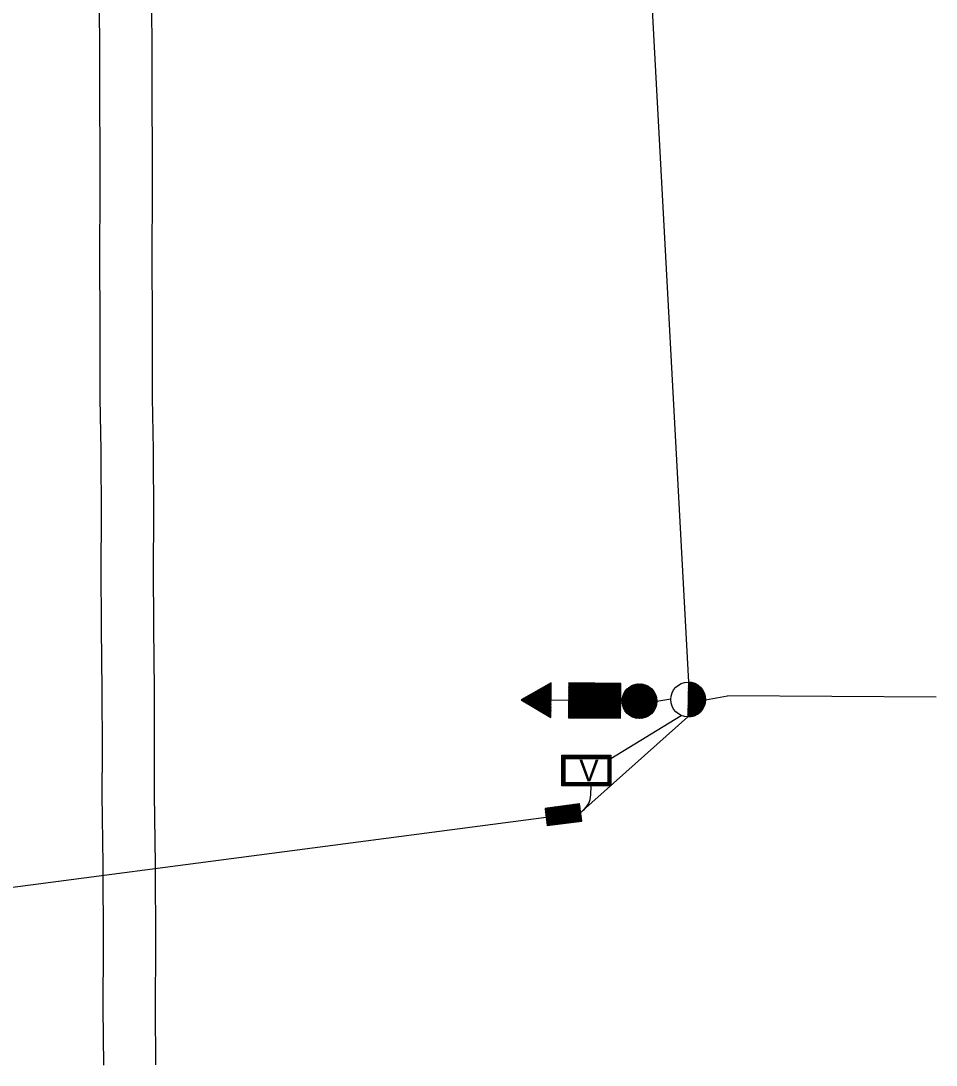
# Model space of a CAD drawing. Extents: x 584850 to 602551, y 145475 to 158627.
# Drawn here: x 585761.3 to 585971.5, y 156212.3 to 156452.1 of the extents above; entities that cross this region are included whole.
import ezdxf

# ---------------------------------------------------------------- set-up
doc = ezdxf.new("R2010")
doc.units = 0
doc.layers.add('Default', color=7, linetype='Continuous')
doc.layers.add('P_ML_LANE_LINE_50', color=7, linetype='Continuous')

msp = doc.modelspace()

# ---------------------------------------------------------------- linework, layer by layer
at = {"layer": 'Default'}
for p, q in [((585893.9, 156683.83), (585914.58, 156300.29)), ((585877.66, 156295.3), (585881.81, 156299.38)), ((585877.87, 156295.18), (585882.62, 156299.84)), ((585878.08, 156295.05), (585883.09, 156299.96)), ((585878.3, 156294.92), (585883.09, 156299.62)), ((585878.51, 156294.8), (585883.08, 156299.28)), ((585883.06, 156297.37), (585881.35, 156299.12)), ((585883.07, 156297.71), (585881.57, 156299.24)), ((585883.07, 156298.05), (585881.79, 156299.36)), ((585883.07, 156298.39), (585882, 156299.48)), ((585883.08, 156298.73), (585882.22, 156299.61)), ((585883.08, 156299.07), (585882.43, 156299.73)), ((585883.09, 156299.41), (585882.65, 156299.85)), ((585883.09, 156299.75), (585882.87, 156299.97)), ((585883.09, 156300.09), (585883.08, 156300.1)), ((585887.01, 156292.1), (585895.09, 156300.02)), ((585887.01, 156292.44), (585894.75, 156300.02)), ((585887.02, 156293.12), (585894.07, 156300.03)), ((585887.02, 156293.45), (585893.73, 156300.03)), ((585887.02, 156292.78), (585894.41, 156300.02)), ((585887.03, 156294.13), (585893.05, 156300.04)), ((585887.03, 156294.47), (585892.72, 156300.04)), ((585887.03, 156293.79), (585893.39, 156300.03)), ((585887.04, 156295.15), (585892.04, 156300.05)), ((585887.04, 156294.81), (585892.38, 156300.04)), ((585887.05, 156296.17), (585891.02, 156300.06)), ((585887.05, 156295.49), (585891.7, 156300.05)), ((585887.05, 156295.83), (585891.36, 156300.05)), ((585887.06, 156297.19), (585890, 156300.07)), ((585887.06, 156296.51), (585890.68, 156300.06)), ((585887.06, 156296.85), (585890.34, 156300.06)), ((585887.07, 156298.21), (585888.98, 156300.08)), ((585887.07, 156297.53), (585889.66, 156300.07)), ((585887.07, 156297.87), (585889.32, 156300.07)), ((585887.08, 156299.22), (585887.96, 156300.09)), ((585887.08, 156298.88), (585888.3, 156300.08)), ((585887.08, 156298.55), (585888.64, 156300.08)), ((585894.14, 156292.03), (585887.08, 156299.22)), ((585887.09, 156299.56), (585887.62, 156300.09)), ((585887.09, 156299.9), (585887.29, 156300.09)), ((585894.82, 156292.02), (585887.09, 156299.9)), ((585894.48, 156292.02), (585887.09, 156299.56)), ((585895.16, 156292.01), (585887.24, 156300.1)), ((585887.35, 156292.09), (585895.43, 156300.01)), ((585895.5, 156292.01), (585887.58, 156300.09)), ((585887.69, 156292.09), (585895.77, 156300.01)), ((585895.84, 156292.01), (585887.92, 156300.09)), ((585888.03, 156292.09), (585896.11, 156300.01)), ((585896.17, 156292), (585888.26, 156300.09)), ((585888.37, 156292.08), (585896.45, 156300)), ((585896.51, 156292), (585888.6, 156300.08)), ((585888.71, 156292.08), (585896.79, 156300)), ((585896.85, 156292), (585888.93, 156300.08)), ((585889.05, 156292.08), (585897.13, 156300)), ((585897.19, 156291.99), (585889.27, 156300.07)), ((585889.39, 156292.07), (585897.47, 156299.99)), ((585897.53, 156291.99), (585889.61, 156300.07)), ((585889.73, 156292.07), (585897.81, 156299.99)), ((585897.87, 156291.99), (585889.95, 156300.07)), ((585890.07, 156292.07), (585898.15, 156299.99)), ((585898.21, 156291.98), (585890.29, 156300.06)), ((585890.4, 156292.06), (585898.49, 156299.98)), ((585898.55, 156291.98), (585890.63, 156300.06)), ((585890.74, 156292.06), (585898.82, 156299.98)), ((585898.89, 156291.98), (585890.97, 156300.06)), ((585891.08, 156292.06), (585899.09, 156299.9)), ((585899.01, 156292.19), (585891.31, 156300.05)), ((585891.42, 156292.05), (585899.09, 156299.56)), ((585899.02, 156292.53), (585891.65, 156300.05)), ((585891.76, 156292.05), (585899.08, 156299.22)), ((585899.02, 156292.87), (585891.99, 156300.05)), ((585899.02, 156293.21), (585892.33, 156300.04)), ((585899.03, 156293.55), (585892.67, 156300.04)), ((585899.03, 156293.89), (585893.01, 156300.04)), ((585899.03, 156294.23), (585893.35, 156300.03)), ((585899.04, 156294.57), (585893.69, 156300.03)), ((585899.04, 156294.91), (585894.03, 156300.03)), ((585899.04, 156295.25), (585894.36, 156300.02)), ((585899.05, 156295.59), (585894.7, 156300.02)), ((585899.05, 156295.93), (585895.04, 156300.02)), ((585899.05, 156296.27), (585895.38, 156300.01)), ((585899.06, 156296.61), (585895.72, 156300.01)), ((585899.06, 156296.95), (585896.06, 156300.01)), ((585899.06, 156297.29), (585896.4, 156300)), ((585899.07, 156297.62), (585896.74, 156300)), ((585899.07, 156297.96), (585897.08, 156300)), ((585899.07, 156298.3), (585897.42, 156299.99)), ((585899.08, 156298.64), (585897.76, 156299.99)), ((585899.08, 156298.98), (585898.1, 156299.99)), ((585899.09, 156299.32), (585898.44, 156299.98)), ((585899.09, 156299.66), (585898.78, 156299.98)), ((585899.34, 156296.03), (585903.29, 156299.91)), ((585899.35, 156295.71), (585903.61, 156299.89)), ((585899.37, 156296.41), (585902.92, 156299.88)), ((585899.37, 156295.39), (585903.92, 156299.86)), ((585899.42, 156295.11), (585904.21, 156299.8)), ((585899.43, 156296.8), (585902.51, 156299.82)), ((585899.48, 156294.83), (585904.48, 156299.73)), ((585899.57, 156294.58), (585904.74, 156299.65)), ((585899.58, 156297.28), (585902.05, 156299.7)), ((585899.66, 156294.34), (585904.97, 156299.54)), ((585899.76, 156294.1), (585905.21, 156299.44)), ((585899.87, 156297.9), (585901.43, 156299.44)), ((585899.89, 156293.89), (585905.42, 156299.31)), ((585900.02, 156293.68), (585905.62, 156299.17)), ((585906.44, 156293.42), (585900.89, 156299.08)), ((585906.59, 156293.61), (585901.1, 156299.22)), ((585906.72, 156293.82), (585901.3, 156299.35)), ((585906.85, 156294.03), (585901.52, 156299.47)), ((585906.96, 156294.27), (585901.75, 156299.58)), ((585907.06, 156294.51), (585901.99, 156299.68)), ((585907.15, 156294.76), (585902.25, 156299.75)), ((585907.21, 156295.03), (585902.52, 156299.82)), ((585907.28, 156295.31), (585902.81, 156299.87)), ((585907.3, 156295.63), (585903.12, 156299.9)), ((585907.32, 156295.95), (585903.45, 156299.91)), ((585907.29, 156296.33), (585903.82, 156299.87)), ((585907.24, 156296.72), (585904.22, 156299.8)), ((585907.1, 156297.21), (585904.68, 156299.68)), ((585906.83, 156297.83), (585905.29, 156299.4)), ((585914.58, 156300.29), (585914.43, 156292.29)), ((585914.51, 156296.63), (585917.21, 156299.22)), ((585914.51, 156296.29), (585917.38, 156299.06)), ((585914.52, 156297.31), (585916.84, 156299.53)), ((585914.52, 156296.97), (585917.02, 156299.38)), ((585914.53, 156297.65), (585916.63, 156299.66)), ((585914.54, 156298.32), (585916.19, 156299.91)), ((585914.54, 156297.99), (585916.41, 156299.79)), ((585914.55, 156298.66), (585915.94, 156300.01)), ((585914.56, 156299.34), (585915.42, 156300.17)), ((585914.56, 156299), (585915.69, 156300.1)), ((585918.4, 156295.36), (585914.56, 156299.34)), ((585914.57, 156299.68), (585915.13, 156300.23)), ((585918.44, 156295.66), (585914.57, 156299.68)), ((585914.58, 156300.29), (585914.58, 156300.29)), ((585914.58, 156300.29), (585914.58, 156300.29)), ((585914.58, 156300.02), (585914.84, 156300.27)), ((585918.49, 156295.96), (585914.58, 156300.02)), ((585918.49, 156296.3), (585914.66, 156300.28)), ((585918.48, 156296.66), (585915.02, 156300.25)), ((585918.41, 156297.08), (585915.43, 156300.17)), ((585918.29, 156297.55), (585915.91, 156300.02)), ((585918.02, 156298.17), (585916.53, 156299.72)), ((585876.37, 156296.06), (585876.97, 156296.65)), ((585876.59, 156295.94), (585877.78, 156297.1)), ((585876.8, 156295.81), (585878.58, 156297.56)), ((585877.01, 156295.68), (585879.39, 156298.01)), ((585879.36, 156294.3), (585877.02, 156296.68)), ((585877.23, 156295.56), (585880.2, 156298.47)), ((585880.15, 156293.83), (585877.24, 156296.8)), ((585877.44, 156295.43), (585881.01, 156298.92)), ((585880.95, 156293.36), (585877.46, 156296.92)), ((585881.75, 156292.88), (585877.67, 156297.04)), ((585882.55, 156292.41), (585877.89, 156297.17)), ((585883.01, 156292.28), (585878.11, 156297.29)), ((585883.02, 156292.62), (585878.32, 156297.41)), ((585883.02, 156292.96), (585878.54, 156297.53)), ((585878.73, 156294.67), (585883.08, 156298.94)), ((585883.02, 156293.3), (585878.76, 156297.65)), ((585878.94, 156294.55), (585883.08, 156298.6)), ((585883.03, 156293.64), (585878.97, 156297.78)), ((585879.15, 156294.42), (585883.07, 156298.26)), ((585883.03, 156293.98), (585879.19, 156297.9)), ((585879.37, 156294.29), (585883.07, 156297.92)), ((585883.03, 156294.32), (585879.41, 156298.02)), ((585879.58, 156294.17), (585883.07, 156297.58)), ((585883.04, 156294.66), (585879.62, 156298.14)), ((585879.79, 156294.04), (585883.06, 156297.24)), ((585883.04, 156295), (585879.84, 156298.26)), ((585880.01, 156293.91), (585883.06, 156296.9)), ((585883.04, 156295.34), (585880.05, 156298.39)), ((585883.05, 156295.68), (585880.27, 156298.51)), ((585883.05, 156296.01), (585880.49, 156298.63)), ((585883.05, 156296.35), (585880.7, 156298.75)), ((585883.06, 156296.69), (585880.92, 156298.87)), ((585883.06, 156297.03), (585881.14, 156299)), ((585892.1, 156292.05), (585887.06, 156297.19)), ((585891.76, 156292.05), (585887.06, 156296.85)), ((585893.12, 156292.04), (585887.07, 156298.21)), ((585892.78, 156292.04), (585887.07, 156297.87)), ((585892.44, 156292.04), (585887.07, 156297.53)), ((585893.8, 156292.03), (585887.08, 156298.88)), ((585893.46, 156292.03), (585887.08, 156298.55)), ((585892.1, 156292.05), (585899.08, 156298.89)), ((585892.44, 156292.04), (585899.08, 156298.55)), ((585892.78, 156292.04), (585899.07, 156298.21)), ((585893.12, 156292.04), (585899.07, 156297.87)), ((585893.46, 156292.03), (585899.07, 156297.53)), ((585893.8, 156292.03), (585899.06, 156297.19)), ((585894.14, 156292.03), (585899.06, 156296.85)), ((585904.13, 156292.01), (585899.43, 156296.81)), ((585904.4, 156292.07), (585899.51, 156297.07)), ((585904.66, 156292.16), (585899.59, 156297.32)), ((585904.91, 156292.24), (585899.69, 156297.56)), ((585905.13, 156292.36), (585899.81, 156297.79)), ((585905.35, 156292.48), (585899.93, 156298.01)), ((585905.56, 156292.6), (585900.07, 156298.21)), ((585900.16, 156293.48), (585905.82, 156299.03)), ((585905.75, 156292.75), (585900.21, 156298.41)), ((585900.32, 156293.3), (585906, 156298.87)), ((585905.94, 156292.9), (585900.36, 156298.6)), ((585900.47, 156293.12), (585906.17, 156298.7)), ((585906.12, 156293.06), (585900.54, 156298.76)), ((585900.65, 156292.96), (585906.35, 156298.54)), ((585906.28, 156293.24), (585900.71, 156298.93)), ((585900.84, 156292.8), (585906.49, 156298.34)), ((585901.02, 156292.65), (585906.63, 156298.14)), ((585901.23, 156292.52), (585906.77, 156297.94)), ((585901.45, 156292.4), (585906.88, 156297.72)), ((585901.67, 156292.28), (585906.99, 156297.49)), ((585901.92, 156292.18), (585907.09, 156297.25)), ((585902.17, 156292.09), (585907.17, 156296.99)), ((585902.44, 156292.02), (585907.24, 156296.73)), ((585914.44, 156292.9), (585918.47, 156296.78)), ((585914.45, 156293.57), (585918.36, 156297.34)), ((585914.45, 156293.23), (585918.42, 156297.06)), ((585914.46, 156293.91), (585918.28, 156297.59)), ((585914.47, 156294.59), (585918.08, 156298.07)), ((585914.47, 156294.25), (585918.18, 156297.83)), ((585914.48, 156294.93), (585917.96, 156298.28)), ((585914.49, 156295.61), (585917.69, 156298.69)), ((585914.49, 156295.27), (585917.83, 156298.49)), ((585914.5, 156295.95), (585917.54, 156298.88)), ((585917.74, 156293.96), (585914.52, 156297.31)), ((585917.6, 156293.77), (585914.52, 156296.97)), ((585917.89, 156294.16), (585914.53, 156297.65)), ((585918.12, 156294.61), (585914.54, 156298.32)), ((585918.01, 156294.38), (585914.54, 156297.99)), ((585918.23, 156294.85), (585914.55, 156298.66)), ((585918.31, 156295.1), (585914.56, 156299)), ((585918.5, 156296.21), (585923.55, 156297.1)), ((585876.16, 156296.19), (585876.16, 156296.19)), ((585876.96, 156295.72), (585876.38, 156296.31)), ((585877.76, 156295.24), (585876.59, 156296.43)), ((585878.56, 156294.77), (585876.81, 156296.56)), ((585880.22, 156293.79), (585883.06, 156296.56)), ((585880.44, 156293.66), (585883.05, 156296.22)), ((585880.65, 156293.53), (585883.05, 156295.89)), ((585880.86, 156293.41), (585883.05, 156295.55)), ((585881.08, 156293.28), (585883.04, 156295.21)), ((585881.29, 156293.15), (585883.04, 156294.87)), ((585881.51, 156293.03), (585883.04, 156294.53)), ((585887.05, 156296.1), (585883.05, 156296.14)), ((585889.39, 156292.07), (585887.03, 156294.47)), ((585890.07, 156292.07), (585887.04, 156295.15)), ((585889.73, 156292.07), (585887.04, 156294.81)), ((585891.08, 156292.06), (585887.05, 156296.17)), ((585890.74, 156292.06), (585887.05, 156295.83)), ((585890.4, 156292.06), (585887.05, 156295.49)), ((585891.42, 156292.05), (585887.06, 156296.51)), ((585894.48, 156292.02), (585899.06, 156296.51)), ((585894.82, 156292.02), (585899.05, 156296.17)), ((585895.16, 156292.01), (585899.05, 156295.83)), ((585895.5, 156292.01), (585899.05, 156295.49)), ((585895.84, 156292.01), (585899.04, 156295.15)), ((585896.17, 156292), (585899.04, 156294.81)), ((585896.51, 156292), (585899.04, 156294.47)), ((585903.54, 156291.93), (585899.34, 156296.21)), ((585903.2, 156291.93), (585899.34, 156295.87)), ((585902.84, 156291.95), (585899.35, 156295.51)), ((585903.84, 156291.96), (585899.38, 156296.51)), ((585902.43, 156292.03), (585899.43, 156295.09)), ((585901.95, 156292.17), (585899.55, 156294.62)), ((585902.73, 156291.97), (585907.28, 156296.43)), ((585903.03, 156291.93), (585907.31, 156296.13)), ((585903.37, 156291.93), (585907.31, 156295.79)), ((585903.73, 156291.94), (585907.29, 156295.43)), ((585904.14, 156292.01), (585907.21, 156295.01)), ((585904.62, 156292.15), (585907.07, 156294.55)), ((585910.51, 156296.36), (585907.33, 156295.87)), ((585914.44, 156292.56), (585918.49, 156296.46)), ((585916.28, 156292.71), (585914.47, 156294.59)), ((585916.05, 156292.61), (585914.47, 156294.25)), ((585916.5, 156292.83), (585914.48, 156294.93)), ((585916.91, 156293.1), (585914.49, 156295.61)), ((585916.71, 156292.97), (585914.49, 156295.27)), ((585917.09, 156293.25), (585914.5, 156295.95)), ((585917.45, 156293.58), (585914.51, 156296.63)), ((585917.27, 156293.42), (585914.51, 156296.29)), ((585914.51, 156292.29), (585918.5, 156296.13)), ((585914.88, 156292.32), (585918.46, 156295.76)), ((585915.29, 156292.38), (585918.4, 156295.37)), ((585915.75, 156292.49), (585918.24, 156294.89)), ((585916.37, 156292.75), (585917.95, 156294.27)), ((585881.72, 156292.9), (585883.03, 156294.19)), ((585881.93, 156292.78), (585883.03, 156293.85)), ((585882.15, 156292.65), (585883.03, 156293.51)), ((585882.36, 156292.52), (585883.02, 156293.17)), ((585882.58, 156292.4), (585883.02, 156292.83)), ((585882.79, 156292.27), (585883.02, 156292.49)), ((585883, 156292.14), (585883.01, 156292.15)), ((585887.35, 156292.09), (585887.01, 156292.44)), ((585888.37, 156292.08), (585887.02, 156293.45)), ((585888.03, 156292.09), (585887.02, 156293.12)), ((585887.69, 156292.09), (585887.02, 156292.78)), ((585889.05, 156292.08), (585887.03, 156294.13)), ((585888.71, 156292.08), (585887.03, 156293.79)), ((585890.29, 156270.71), (585914.43, 156292.29)), ((585896.8, 156282.71), (585912.91, 156292.62)), ((585896.85, 156292), (585899.03, 156294.13)), ((585897.19, 156291.99), (585899.03, 156293.79)), ((585897.53, 156291.99), (585899.03, 156293.45)), ((585897.87, 156291.99), (585899.02, 156293.12)), ((585898.21, 156291.98), (585899.02, 156292.78)), ((585898.55, 156291.98), (585899.02, 156292.44)), ((585898.89, 156291.98), (585899.01, 156292.1)), ((585901.33, 156292.46), (585899.83, 156294)), ((585905.25, 156292.42), (585906.79, 156293.93)), ((585914.47, 156292.29), (585914.43, 156292.33)), ((585914.99, 156292.33), (585914.44, 156292.9)), ((585914.68, 156292.31), (585914.44, 156292.56)), ((585915.55, 156292.44), (585914.45, 156293.57)), ((585915.28, 156292.37), (585914.45, 156293.23)), ((585915.81, 156292.51), (585914.46, 156293.91)), ((585892.17, 156274.41), (585892.25, 156276.44)), ((585881.7, 156271.03), (585881.92, 156271.33)), ((585885.88, 156267.82), (585881.7, 156271.03)), ((585886.22, 156267.86), (585881.73, 156271.3)), ((585881.74, 156270.69), (585882.26, 156271.37)), ((585885.55, 156267.77), (585881.74, 156270.69)), ((585881.78, 156270.36), (585882.6, 156271.42)), ((585885.21, 156267.73), (585881.78, 156270.36)), ((585881.83, 156270.02), (585882.93, 156271.46)), ((585881.87, 156269.69), (585883.27, 156271.51)), ((585881.92, 156269.35), (585883.61, 156271.55)), ((585881.96, 156269.01), (585883.94, 156271.6)), ((585882.01, 156268.68), (585884.28, 156271.64)), ((585882.05, 156268.34), (585884.62, 156271.68)), ((585886.56, 156267.9), (585882.07, 156271.35)), ((585882.09, 156268), (585884.95, 156271.73)), ((585882.14, 156267.67), (585885.29, 156271.77)), ((585882.18, 156267.33), (585885.63, 156271.82)), ((585886.89, 156267.95), (585882.41, 156271.39)), ((585882.52, 156267.37), (585885.96, 156271.86)), ((585887.23, 156267.99), (585882.74, 156271.44)), ((585882.86, 156267.42), (585886.3, 156271.91)), ((585887.57, 156268.04), (585883.08, 156271.48)), ((585883.19, 156267.46), (585886.64, 156271.95)), ((585887.9, 156268.08), (585883.42, 156271.53)), ((585883.53, 156267.51), (585886.97, 156271.99)), ((585888.24, 156268.13), (585883.75, 156271.57)), ((585883.86, 156267.55), (585887.31, 156272.04)), ((585888.58, 156268.17), (585884.09, 156271.61)), ((585884.2, 156267.6), (585887.65, 156272.08)), ((585888.91, 156268.21), (585884.42, 156271.66)), ((585884.54, 156267.64), (585887.98, 156272.13)), ((585889.25, 156268.26), (585884.76, 156271.7)), ((585884.87, 156267.68), (585888.32, 156272.17)), ((585889.59, 156268.3), (585885.1, 156271.75)), ((585885.21, 156267.73), (585888.65, 156272.22)), ((585889.92, 156268.35), (585885.43, 156271.79)), ((585885.55, 156267.77), (585888.99, 156272.26)), ((585890.09, 156268.52), (585885.77, 156271.84)), ((585885.88, 156267.82), (585889.33, 156272.3)), ((585890.05, 156268.85), (585886.11, 156271.88)), ((585886.22, 156267.86), (585889.6, 156272.27)), ((585890.01, 156269.19), (585886.44, 156271.92)), ((585886.56, 156267.9), (585889.65, 156271.93)), ((585889.96, 156269.53), (585886.78, 156271.97)), ((585886.89, 156267.95), (585889.69, 156271.59)), ((585889.92, 156269.86), (585887.12, 156272.01)), ((585887.23, 156267.99), (585889.73, 156271.26)), ((585889.87, 156270.2), (585887.45, 156272.06)), ((585887.57, 156268.04), (585889.78, 156270.92)), ((585889.83, 156270.54), (585887.79, 156272.1)), ((585887.9, 156268.08), (585889.82, 156270.58)), ((585889.78, 156270.87), (585888.13, 156272.15)), ((585889.74, 156271.21), (585888.46, 156272.19)), ((585889.7, 156271.55), (585888.8, 156272.23)), ((585889.65, 156271.88), (585889.14, 156272.28)), ((585889.61, 156272.22), (585889.47, 156272.32)), ((585889.85, 156270.36), (585890.29, 156270.71)), ((585616.41, 156234.38), (585881.92, 156269.31)), ((585884.87, 156267.68), (585881.83, 156270.02)), ((585884.54, 156267.64), (585881.87, 156269.69)), ((585884.2, 156267.6), (585881.92, 156269.35)), ((585883.86, 156267.55), (585881.96, 156269.01)), ((585883.53, 156267.51), (585882.01, 156268.68)), ((585883.19, 156267.46), (585882.05, 156268.34)), ((585882.86, 156267.42), (585882.09, 156268)), ((585888.24, 156268.13), (585889.87, 156270.25)), ((585888.58, 156268.17), (585889.91, 156269.91)), ((585888.91, 156268.21), (585889.96, 156269.57)), ((585889.25, 156268.26), (585890, 156269.24)), ((585889.59, 156268.3), (585890.04, 156268.9)), ((585889.92, 156268.35), (585890.09, 156268.56)), ((585882.52, 156267.37), (585882.14, 156267.67))]:
    msp.add_line(p, q, dxfattribs=at)
for points in [[(585883.01, 156292.14), (585883.09, 156300.1), (585876.16, 156296.19)], [(585899.09, 156299.98), (585887.09, 156300.1), (585887.01, 156292.1), (585899.01, 156291.98)], [(585885.5, 156283.49), (585896.8, 156283.49), (585896.8, 156276.44), (585885.5, 156276.44)], [(585885.75, 156283.24), (585896.55, 156283.24), (585896.55, 156276.69), (585885.75, 156276.69)], [(585886, 156282.99), (585896.3, 156282.99), (585896.3, 156276.94), (585886, 156276.94)], [(585886.25, 156282.74), (585896.05, 156282.74), (585896.05, 156277.19), (585886.25, 156277.19)], [(585889.59, 156272.34), (585881.66, 156271.3), (585882.18, 156267.33), (585890.11, 156268.37)]]:
    msp.add_lwpolyline(points, close=True, dxfattribs=at)
msp.add_lwpolyline([(585971.47, 156296.84), (585923.55, 156297.1)], dxfattribs=at)
for centre in [(585903.33, 156295.91), (585914.51, 156296.29)]:
    msp.add_circle(centre, 4, dxfattribs=at)
for centre, radius, start, end in [((585914.51, 156296.29), 4, 268.9257, 88.9257), ((585887.17, 156274.62), 5, 308.5959, 357.6663)]:
    msp.add_arc(centre, radius, start, end, dxfattribs=at)
at = {"layer": 'P_ML_LANE_LINE_50'}
for points in [[(585780.31, 156212.33), (585780.21, 156225.36), (585780.29, 156239.83), (585780.19, 156258.39), (585779.95, 156274.44), (585779.99, 156284.52), (585779.94, 156298.41), (585779.78, 156312.7), (585779.74, 156326.93), (585779.78, 156337.72), (585779.7, 156353.5), (585779.49, 156365.49), (585779.47, 156382.8), (585779.4, 156397.71), (585779.48, 156413.36), (585779.41, 156442.31), (585779.36, 156458.78)], [(585792.31, 156212.43), (585792.21, 156225.37), (585792.29, 156239.83), (585792.19, 156258.51), (585791.95, 156274.51), (585791.99, 156284.51), (585791.94, 156298.51), (585791.78, 156312.78), (585791.74, 156326.92), (585791.78, 156337.73), (585791.7, 156353.63), (585791.49, 156365.6), (585791.47, 156382.84), (585791.4, 156397.7), (585791.48, 156413.35), (585791.41, 156442.34), (585791.36, 156458.83)]]:
    msp.add_lwpolyline(points, dxfattribs=at)

# ---------------------------------------------------------------- texts
at = {"layer": 'Default'}
msp.add_text('V', height=4.96, rotation=360, dxfattribs=at).set_placement((585889.53, 156277.49))

doc.saveas('drawing.dxf')
